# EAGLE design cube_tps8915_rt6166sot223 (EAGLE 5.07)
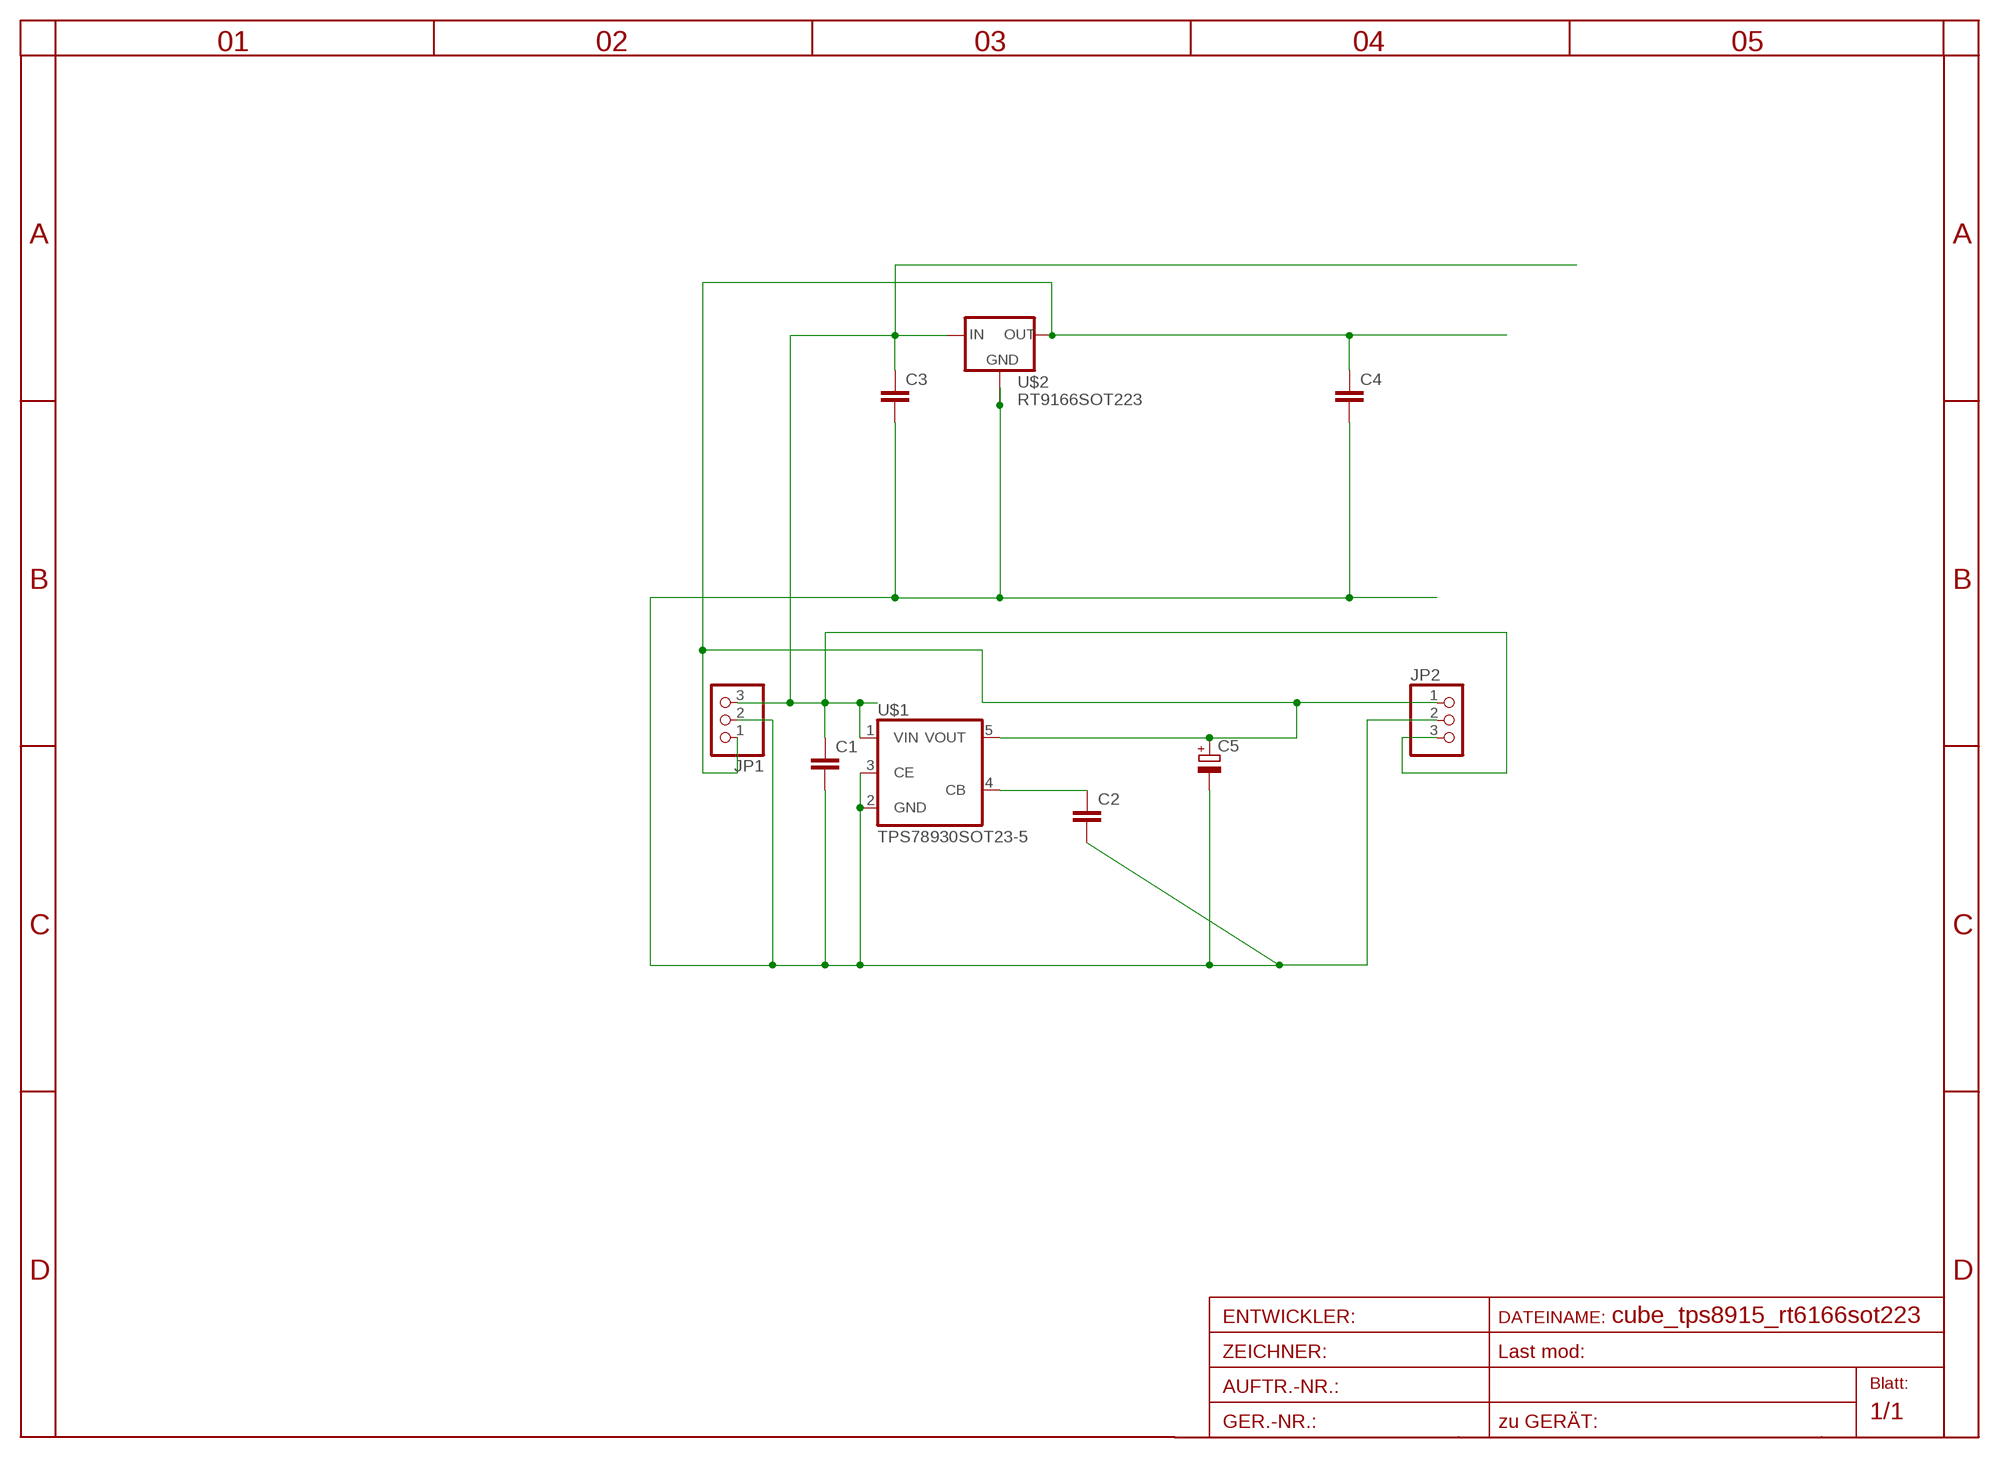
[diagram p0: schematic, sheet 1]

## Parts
C1  C-EUC1206  [C1206]
C2  C-EUC0805  [C0805]
C3  C-EUC1206  [C1206]
C4  C-EUC1206  [C1206]
C5  CPOL-EUSMCA  [SMC_A]
JP1  PINHD-1X3  [1X03]
JP2  PINHD-1X3  [1X03]
U$1  TPS78930SOT23-5  [SOT25]
U$2  RT9166SOT223  [SOT223]

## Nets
GND: C1.2 C2.2 C3.2 C4.2 C5.- JP1.2 JP2.2 U$1.2(GND) U$1.3(CE) U$2.2(GND) U$2.4(GND1)
IN: C1.1 C3.1 JP1.3 JP2.3 U$1.1(VIN) U$2.3(IN)
N$1: C2.1 U$1.4(CB)
OUT: C4.1 C5.+ JP1.1 JP2.1 U$1.5(VOUT) U$2.1(OUT)

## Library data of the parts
C1-C4 = rcl:C-EU: CAPACITOR, European symbol
C5 = rcl:CPOL-EU: POLARIZED CAPACITOR, European symbol
JP1 JP2 = pinhead:PINHD-1X3: PIN HEADER
U$1 = v-reg:TPS78930
U$2 = v-reg:RT9166

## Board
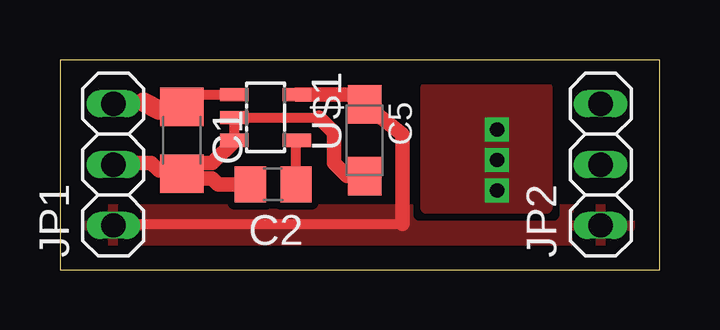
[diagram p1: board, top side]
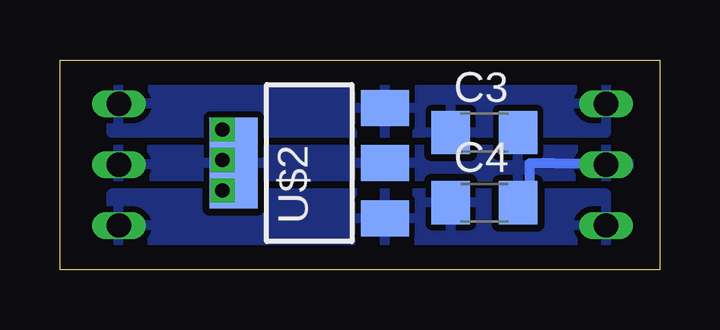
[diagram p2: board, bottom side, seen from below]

Size 25 x 8.75 mm. Coordinates in mm from the lower left corner, seen from the top.
Outline: 0,0 25,0 25,8.75 0,8.75 0,0
Copper layers (1*16): Top 0.035mm / dielectric 1.5mm / Bottom 0.035mm
Design rules "default": minimum track width 10mil, minimum drill 20mil, track to track 8mil, track to pad 8mil, pad to pad 8mil, via to via 8mil, smd to smd 8mil, copper to edge 40mil, drill to drill 8mil, minimum pad ring 1mil, minimum via ring 8mil, stop-mask expansion 4mil, vias tented up to drill 0mil, thermal gap 10mil

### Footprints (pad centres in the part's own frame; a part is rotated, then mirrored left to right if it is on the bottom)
C1206 = smd 1.6 x 1.8: 1 -1.4,0; 2 1.4,0
C0805 = smd 1.3 x 1.5: 1 -0.95,0; 2 0.95,0
SMC_A = smd 1.6 x 1.4: + -1.5,0; - 1.5,0
1X03 = drill 1.016 long: 1 -2.54,0; 2 0,0; 3 2.54,0
SOT25 = smd 0.55 x 1.2: 1 -0.95,-1.3; 2 0,-1.3; 3 0.95,-1.3; 4 0.95,1.3; 5 -0.95,1.3
SOT223 = smd 1.5 x 2: 1 -2.3,-3.15; 2 0,-3.15; 3 2.3,-3.15 | smd 3.8 x 2: 4 0,3.15

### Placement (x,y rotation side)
C1  5.08,5.4 270 top
C2  8.89,3.56 180 top
C3  7.3,5.71 0 bottom
C4  7.3,2.79 0 bottom
C5  12.7,5.4 270 top
JP1  2.22,4.38 90 top
JP2  22.54,4.38 90 top
U$1  8.57,6.35 270 top
U$2  14.61,4.45 90 bottom

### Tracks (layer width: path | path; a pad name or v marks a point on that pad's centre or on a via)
GND  (via drill 0.6)
  Top 0.406: 4.13,4.13 C1.2 | JP1.2 2.29,4.45 | C1.2 5.27,3.81 | 7.27,5.37 U$1.3 U$1.2 10.79,6.35 | C1.2 5.53,4.45 | 11.98,3.9 C5.-
  Top 0.61: 4.13,4.13 3.81,4.45 2.29,4.45 | C2.2 6.6,3.56 6.35,3.81 5.27,3.81 | 7.27,5.37 6.35,4.45 5.53,4.45 | 11.98,3.9 11.43,4.45 11.43,5.71 10.79,6.35
  Bottom 0.406: C4.2 5.42,2.79 5.42,4.45 JP1.2
  other vias: 18.22,5.84 18.22,4.57 18.22,3.3
  pour Bottom (isolate 0.305, rank 2): 1.27,5.08 11.43,5.08 12.7,5.71 22.86,5.71 22.86,3.17 13.97,3.17 12.7,3.81 1.27,3.81
  pour Top: 15.24,7.62 20.32,7.62 20.32,2.54 15.24,2.54
IN
  Top 0.406: 4.13,6.67 C1.1 5.71,7.3 U$1.1 | 3.49,6.99 2.29,6.99 JP1.3
  Top 0.813: 3.49,6.99 4.13,6.67
  pour Bottom (isolate 0.254): 2.22,5.71 2.22,8.26 22.86,8.26 22.86,5.71
N$1
  Top 0.406: C2.1 9.84,5.37 U$1.4
OUT
  Top 0.406: C5.+ 12.7,7.3 | 14.29,1.91 2.22,1.91 JP1.1
  Top 0.61: 12.7,7.3 U$1.5 | C5.+ 14.29,5.63 14.29,1.91
  pour Top (isolate 0.305, rank 2): 0.95,1.59 0.95,2.22 1.27,2.54 23.5,2.54 23.81,2.22 23.81,1.91 23.18,0.64 1.27,0.64
  pour Bottom (isolate 0.305): 2.22,0.64 2.22,3.17 22.86,3.17 22.86,0.64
